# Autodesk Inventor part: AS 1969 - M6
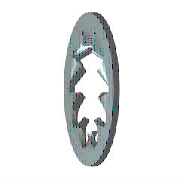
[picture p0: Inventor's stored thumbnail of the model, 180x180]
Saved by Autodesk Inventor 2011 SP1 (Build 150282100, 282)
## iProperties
Created: 2010-02
Part Number: AS 1969 - M6
Material: Steel, Mild
Description: Tooth lock washers (metric series)
Document SubType Name: Modeling
Standard: AS 1969
Designer: sdarley
Standards Organization: AS
Language: en-US
Size Designation: M6
Categories: <MemberInstance><Categories><Category DisplayName="Fasteners" InternalName="e4da775c-781d-43d5-af7c-5136215cf5a6" Mnemonic="FSTN"><Category DisplayName="Washers
Density: 1 g/cm^3
IsCustomPart: 0
Author: sdarley
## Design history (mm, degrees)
pattern_circular "Cuts" dims angle "d11" = 360 deg
body "Solid1"
sketch "Sketch1"
  geometry: C1 r 5.5 at (0, 0); C2 r 3.2 at (0, 0); 1 further point
  constraints: 2 centre point, 2 coincident
  dimensions: "d0" = 11 diameter of C1 (= SD2); "d1" = 6.4 diameter of C2 (= SD1)
extrude "Body" new body sketch "Sketch1" distance "d2" = 0.75 (= SD); taper "d3" = 0 deg
sketch "Sketch2"
  geometry: L1 (-0.624, 3.139)-(-0.849, 4.266); L2 (0, 0)-(0, 4.35); L3 (0.624, 3.139)-(0.849, 4.266); L4 (-0.624, 3.139)-(0, 0); L5 (0.624, 3.139)-(0, 0); C1 r 5.5 at (0, 0) reference; A1 r 3.2 centre (0, 0) between (-0.624, 3.139) and (0.624, 3.139) reference; A2 r 4.35 centre (0, 0) between (0.849, 4.266) and (-0.849, 4.266)
  constraints: 10 end point, 5 point on circle, 1 centre point, 1 coincident, 1 collinear, 1 symmetric about line, 1 vertical, 2 other
  dimensions: "d4" = 8.7 diameter of A2 (= 0.5 x SD2 + 0.5 x SD1); "d5" = 11.25 deg angle of L2 L1 (computed from SAZ)
extrude "Cut" cut sketch "Sketch2" distance "d6" = 0.75 (= SD); taper "d7" = 0 deg
workplane "Work Plane1"
fillet "Fillet1" dims "d8" = 0.192 (= 0.03 x SD1)
other parameters: "SD1" = 6.4 [user parameter; used in 3 equation terms], "SD2" = 11 [user parameter; used in 2 equation terms], "SD" = 0.75 [user parameter; used in 2 equation terms], "d12" = 0, "d13" = 0, "d18" = 0, "d19" = 0, "NND" = 6 [user parameter]
